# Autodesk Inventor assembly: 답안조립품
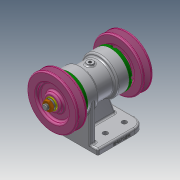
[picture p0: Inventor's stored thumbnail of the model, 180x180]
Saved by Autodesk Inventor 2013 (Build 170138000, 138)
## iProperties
Created: 2020-06
Part Number: 답안조립품
Document SubType Name: Assembly
Designer: user
Author: user
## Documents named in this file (12)
- C:\Users\user\Desktop\700606V1041\답안조립품.iam
- C:\Users\user\Desktop\700606V1041\본체.ipt
- C:\Users\user\Desktop\700606V1041\Ű 5x5x12.ipt
- C:\Users\user\Desktop\700606V1041\V-벨트풀리.ipt
- C:\Users\user\Desktop\700606V1041\너트 M10.ipt
- C:\Users\user\Desktop\700606V1041\베어링 6204.ipt
- C:\Users\user\Desktop\700606V1041\볼트 M4.ipt
- C:\Users\user\Desktop\700606V1041\스프링 와셔 10.ipt
- C:\Users\user\Desktop\700606V1041\오일 실 20 32 5.ipt
- C:\Users\user\Desktop\700606V1041\축.ipt
- C:\Users\user\Desktop\700606V1041\커버.ipt
- C:\Users\user\Desktop\700606V1041\평면 와셔 10x21.ipt
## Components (4 placed, 2 different names)
1. Ű 5x5x12:1
2. V-벨트풀리:1
3. Ű 5x5x12:2
4. V-벨트풀리:2
